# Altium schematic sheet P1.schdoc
size 297 x 209 mm; Symbol: Drawing-Symbol_A4; @Project Name: ThermalInversion; @Page Count: 1; @Update Date: 2026-10-27; @Create Date: 2026-10-27; @Schematic Name: Schematic1; @Page No: 1; @Page Name: P1; Company: EasyEDA.com; Version: V1.0; Page Size: A4; Device: Drawing-Symbol_A4; @Create Time: 09:02:32; @Update Time: 09:02:32; Border: 1; Width: 1170; Height: 825; Region Start: 1; X Region Count: 6; Y Region Count: 4; Blade Width: 10; Title Block Position: 3
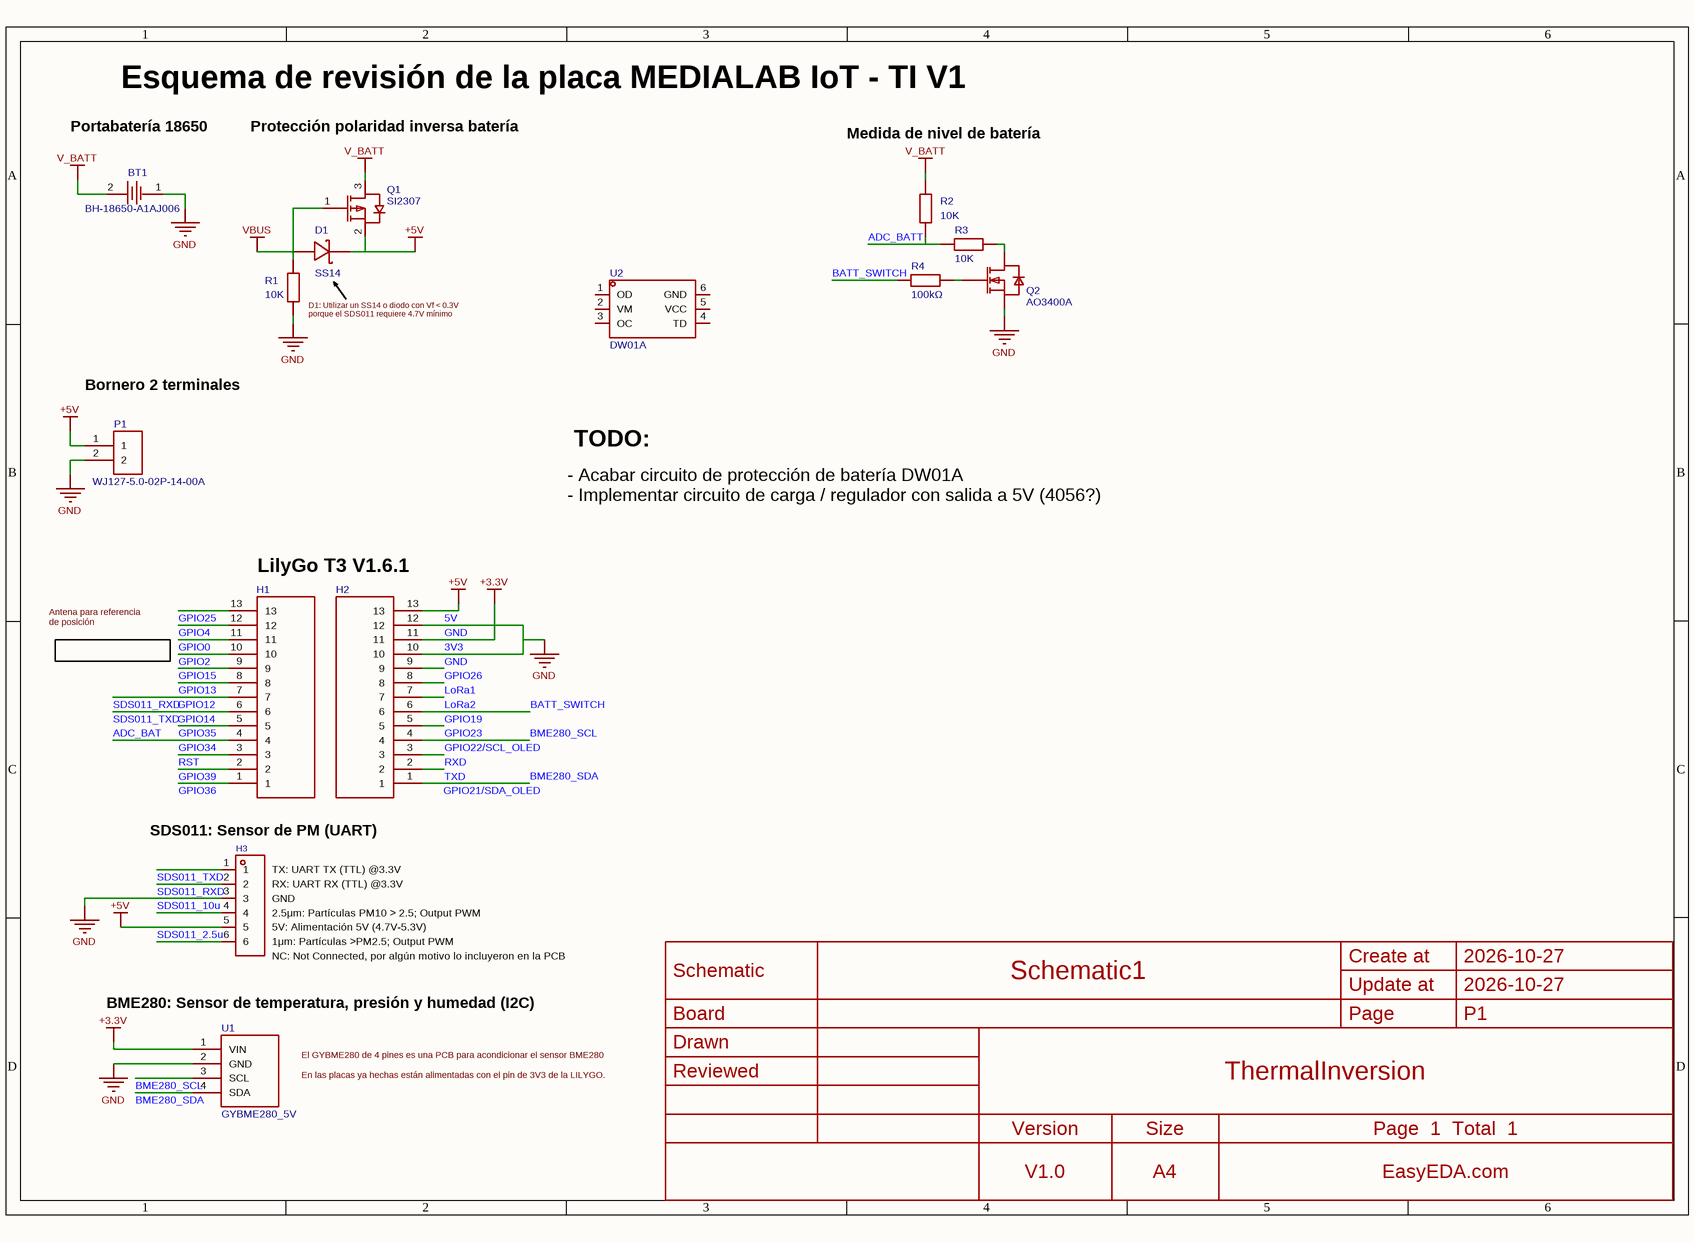
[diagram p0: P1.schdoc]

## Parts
BT1  BH-18650-A1AJ006  [BAT-TH_BH-18650-A1AJ006]
D1  SS14  [SMA_L4.3-W2.6-LS5.1-RD]
H1  (no value)  [HDR-F_2.54_1x13]
H2  (no value)  [HDR-F_2.54_1x13]
H3  (no value)  [HDR-TH_6P-P2.54-V-F]
P1  WJ127-5.0-02P-14-00A  [CONN-TH_2P-P5.00_CPC3703CTR]
Q1  SI2307  [SOT-23-3_L2.9-W1.3-P1.90-LS2.4-BL-2]
Q2  AO3400A  [SOT-23-3_L2.9-W1.3-P1.90-LS2.4-BR]
R1  10K  [R0603]
R2  10K  [R0603]
R3  10K  [R0603]
R4  100kΩ  [RES-TH_BD3.3-L9.0-P13.00-D0.6]
U1  (no value)  [GYBME280_5V]
U2  DW01A  [SOT-23-6_L2.9-W1.6-P0.95-LS2.8-BL]

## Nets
3V3: H2.11 U1.1(VIN)  [also labelled +3.3V]
5V: D1.1(C) H2.13 H3.5 P1.1 Q1.2(S)  [also labelled +5V]
GND: BT1.1 H2.10 H2.12 H3.3 P1.2 Q2.2(S) R1.2 U1.2(GND)
V_BATT: BT1.2 Q1.3(D) R2.1
VBUS: D1.2(A) Q1.1(G) R1.1
ADC_BAT: H1.4  [also labelled GPIO34]
ADC_BATT: R2.2 R3.1
BATT_SWITCH: H2.6 R4.1  [also labelled GPIO19]
BME280_SCL: H2.4 U1.3(SCL)  [also labelled GPIO22/SCL_OLED]
BME280_SDA: H2.1 U1.4(SDA)  [also labelled GPIO21/SDA_OLED]
GPIO0: H1.11
GPIO2: H1.10
GPIO4: H1.12
GPIO12: H1.7 H3.2  [also labelled SDS011_RXD]
GPIO13: H1.8
GPIO14: H1.6 H3.1  [also labelled SDS011_TXD]
GPIO15: H1.9
GPIO23: H2.5
GPIO25: H1.13
GPIO26: H2.9
GPIO35: H1.5
GPIO36: H1.1
GPIO39: H1.2
LoRa1: H2.8
LoRa2: H2.7
RST: H1.3
RXD: H2.3
SDS011_2.5u: H3.6
SDS011_10u: H3.4
TXD: H2.2
NetQ2_1: Q2.1(G) R4.2
NetQ2_3: Q2.3(D) R3.2

Not connected (* = marked no-connect by the designer): U2 1(OD) 2(VM) 3(OC) 4(TD) 5(VCC) 6(GND)

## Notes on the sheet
- Esquema de revisión de la placa MEDIALAB IoT - TI V1
- Portabatería 18650
- Protección polaridad inversa batería
- (near R2) Medida de nivel de batería
- (near R1) D1: Utilizar un SS14 o diodo con Vf < 0.3V
  porque el SDS011 requiere 4.7V mínimo
- (near P1) Bornero 2 terminales
- TODO:
- - Acabar circuito de protección de batería DW01A
  - Implementar circuito de carga / regulador con salida a 5V (4056?)
- LilyGo T3 V1.6.1
- Antena para referencia
  de posición
- SDS011: Sensor de PM (UART)
- (near H3) TX: UART TX (TTL) @3.3V
- (near H3) 1μm: Partículas >PM2.5; Output PWM
- (near H3) NC: Not Connected, por algún motivo lo incluyeron en la PCB
- (near H3) 5V: Alimentación 5V (4.7V-5.3V)
- (near H3) 2.5μm: Partículas PM10 > 2.5; Output PWM
- (near H3) GND
- (near H3) RX: UART RX (TTL) @3.3V
- BME280: Sensor de temperatura, presión y humedad (I2C)
- El GYBME280 de 4 pines es una PCB para acondicionar el sensor BME280
  En las placas ya hechas están alimentadas con el pin de 3V3 de la LILYGO.

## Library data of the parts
BT1 = BH-18650-A1AJ006: Type:Battery holder Operating Temperature:-10~100℃ Contact coating:Nickel plating; Manufacturer: MYOUNG(美阳); AddInBom: yes; ModelId: 29d8123af44545b1a6ab26a514e5c6c60819f05c4eef4c71ace90d822a990e87; ModelTransform: 2972.435,827.164,0,0,0,0,0,0,-295.275
D1 = SS14_C53064714: Diode Configuration:1 Independent Voltage - Forward(Vf@If):550mV@1A Voltage - DC Reverse(Vr):40V Current - Rectified:1A Reverse Leakage Current (Ir):500uA@40V Operating Junction Temperature Range:-55℃~+125℃ Operating Junction Temperature Range:-55℃~+125℃; Manufacturer: luJing(鲁晶); 3D Model: 9f0f28a3f5e244ceb50a0213b7a9858d0819f05c4eef4c71ace90d822a990e87; 3D Model Transform: 196.4563,102.362,0,0,0,0,0.001,-0.001,0; Voltage - DC Reverse(Vr): 40V; Current - Rectified: 1A; Non-Repetitive Peak Forward Surge Current: 30A; AddInBom: yes
H1 H2 = HDR-F_2.54_1x13: Cabecero hembra de 13 pines a 2.54mm; Convert to PCB: yes
H3 = HDR-F_2.54_1x6P: Manufacturer: BOOMELE(博穆精密); Manufacturer Part: 2.54-1*6P母; Symbol: Header-Female-2.54_1x6; 3D Model: 72da3eac8a074bb0a56a474e38d1760c0819f05c4eef4c71ace90d822a990e87; 3D Model Transform: 619.684,94.488,0,0,0,0,0,0,-125.984; ConvertToPcb: yes
P1 = WJ127-5.0-02P-14-00A: Number of Positions or Pins:1x2P Pitch:5mm Color:Green Mounting Type:Through Hole Number of Pins:2P Number of Rows:1 Number of PINs Per Row:2 Screw Specification:M2.5 Current Rating:15A Voltage Rating (Max):250V Wire Gauge - AWG:14~26 Wire Gauge - mm2:1.5; Manufacturer: KANGNEX(康奈克斯电气); Symbol: WJ127-5.0-2P; AddInBom: yes; ModelId: 0c699dafc1fb4759bdee4490ad46ecba0819f05c4eef4c71ace90d822a990e87; ModelTransform: 416.145,318.897,0,0,0,0,-11.811,5.315,-149.606; Number of Positions or Pins: 1x2P; Pitch: 5mm; Number of PINs Per Row: 2; Screw Specification: M2.5; Current Rating: 15A; Voltage Rating (Max): 250V; Wire Gauge - AWG: 14~26; Wire Gauge - mm2: 1.5
Q1 = SI2307_C46061574: Number:1 P-Channel Drain to Source Voltage:30V Current - Continuous Drain(Id):3A RDS(on):65mΩ@10V Pd - Power Dissipation:1.4W Gate Threshold Voltage (Vgs(th)):1.6V Gate Charge(Qg):2.5nC@4.5V Input Capacitance(Ciss):226pF Reverse Transfer Capacitance (Crss; Manufacturer: GOODWORK(固得沃克); 3D Model: 2b5e0bb6381843289fcf9a198bd1677a0819f05c4eef4c71ace90d822a990e87; 3D Model Transform: 114.173,94.488,0,0,0,0,0,0,0; Drain to Source Voltage: 30V; Current - Continuous Drain(Id): 3A; Pd - Power Dissipation: 1.4W; Gate Threshold Voltage (Vgs(th)): 1.6V; Input Capacitance(Ciss): 226pF; Reverse Transfer Capacitance (Crss@Vds): 29pF; Output Capacitance(Coss): 39pF; AddInBom: yes; ModelName: SOT-23-3_L2.9-W1.3-P1.90-LS2.4
Q2 = AO3400A_C42419946: Number:1 N-channel Drain to Source Voltage:30V Current - Continuous Drain(Id):5.8A RDS(on):52mΩ@2.5V Pd - Power Dissipation:1.4W Gate Threshold Voltage (Vgs(th)):1.4V Input Capacitance(Ciss):1.05nF Reverse Transfer Capacitance (Crss@Vds):77pF Output Capac; Manufacturer: ChipNobo(无边界); AddInBom: yes; ModelId: 62a57c6760504a01965db6419a6d07df0819f05c4eef4c71ace90d822a990e87; ModelName: SOT-23-3P_L2.9-W1.3-H1.0-LS2.4-P0.95; ModelTransform: 98.425,114.173,0,180,0,0,0.0005,-0.0005,0; Drain to Source Voltage: 30V; Current - Continuous Drain(Id): 5.8A; Pd - Power Dissipation: 1.4W; Gate Threshold Voltage (Vgs(th)): 1.4V; Input Capacitance(Ciss): 1.05nF; Reverse Transfer Capacitance (Crss@Vds): 77pF; Output Capacitance(Coss): 99pF
R1-R3 = Res_0603: Symbol: Res; 3D Model: 112863783b5b41f1b5254f87eedc79320819f05c4eef4c71ace90d822a990e87; 3D Model Transform: 31.8897,63.7794,0,90,0,0,0,0,0; ConvertToPcb: yes
R4 = Res_AXIAL-1/2W: Symbol: Res; 3D Model: 44b417013abf4a8cb44436658941ed260819f05c4eef4c71ace90d822a990e87; 3D Model Transform: 535.432,129.82565,0,0,0,0,0,0,-196.85; AddInBom: yes
U1 = GYBME280_5V: PCB con circuito de acondicionamiento para BMP280 con comunicación I2C y alimentación a 5V.; AddInBom: yes
U2 = DW01A_C351410: The Chip Type:Protection IC Voltage - Supply:300mV~10V Voltage - Supply:300mV~10V Charge Current - Max:- Charging Saturation Voltage:4.3V End-Off Voltage:2.5V Type of Battery:Lithium Battery Number of Cells:1 Number of Cells:1 Operating Temperature:-40℃~+; Manufacturer: PUOLOP(迪浦); AddInBom: yes; ModelId: 1370be37a17e44418ae52e2b4cc1f5e50819f05c4eef4c71ace90d822a990e87; ModelName: SOT-23-6_L2.9-W1.6-H1.5-LS2.8-P0.95; ModelTransform: 110.236,113.364,0,90,0,0,0.0005,0.0005,0; Charging Saturation Voltage: 4.3V; End-Off Voltage: 2.5V; Number of Cells: 1; Battery Temperature Detection: Not supported; 0V Battery Charge: Support; Supply Current (Iq): 3uA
